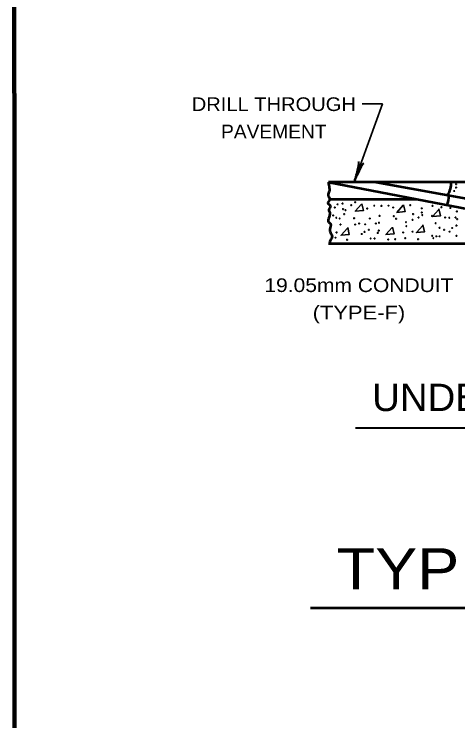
# Model space of a CAD drawing. Extents: x -90 to 623, y -379 to 75.
# Drawn here: x -42.6 to 22.4, y -132.1 to -28.7 of the extents above; entities that cross this region are included whole.
import ezdxf
from ezdxf.enums import TextEntityAlignment as Align

# ---------------------------------------------------------------- set-up
doc = ezdxf.new("R2010")
doc.units = 0
doc.header["$LTSCALE"] = 0.8
doc.layers.add('1', color=7, linetype='Continuous', lineweight=35)

msp = doc.modelspace()

# ---------------------------------------------------------------- linework, layer by layer
at = {"layer": '1', "lineweight": 53}
for p, q in [((33.4567, -53.3181), (3.4567, -53.3181)), ((3.4567, -53.3181), (31.9376, -58.7988)), ((10.4567, -53.3181), (32.4567, -57.3053)), ((3.4567, -55.8181), (16.448, -55.8181)), ((33.4567, -62.3181), (3.4567, -62.3181)), ((0.8544, -115.6087), (216.8702, -115.6087))]:
    msp.add_line(p, q, dxfattribs=at)
at = {"layer": '1', "lineweight": 40}
msp.add_line((7.4085, -89.2559), (100.8059, -89.2559), dxfattribs=at)
at = {"layer": '1', "lineweight": 158}
msp.add_lwpolyline([(617.1938, 69.4188), (-42.5562, 69.3355), (-42.4728, -368.9978)], dxfattribs=at)
at = {"layer": '1'}
for points in [[(7.2722, -53.1423), (11.3764, -41.866), (8.3764, -41.866)], [(8.3163, -56.5358), (7.3949, -57.5722), (8.5849, -57.4571), (8.3546, -56.459)], [(14.4199, -56.6893), (13.4986, -57.7258), (14.6886, -57.6107), (14.4582, -56.6126)], [(19.6023, -57.3035), (18.681, -58.34), (19.871, -58.2248), (19.6407, -57.2267)], [(6.2432, -60.0291), (5.3219, -61.0656), (6.5119, -60.9504), (6.2816, -59.9523)], [(12.8077, -59.9523), (11.8863, -60.9888), (13.0763, -60.8737), (12.846, -59.8756)], [(17.2607, -59.6452), (16.3393, -60.6817), (17.5293, -60.5665), (17.299, -59.5684)]]:
    msp.add_lwpolyline(points, dxfattribs=at)
for centre in [(22.1552, -53.5987), (21.8865, -54.5968), (22.1552, -54.0977), (4.8038, -56.5547), (5.5332, -56.4395), (6.8, -56.6698), (7.3758, -56.2475), (10.1782, -56.7466), (11.2147, -56.785), (12.2512, -56.7466), (15.4373, -56.6698), (18.7003, -56.785), (4.3816, -57.0153), (5.61, -57.2457), (5.7636, -57.975), (5.9555, -57.3992), (9.1417, -57.1688), (12.9422, -57.0153), (15.8596, -57.975), (17.1264, -57.1305), (17.1264, -57.7447), (20.0055, -56.9769), (21.3107, -57.0921), (22.2704, -57.5911), (4.1513, -58.1669), (4.6119, -58.5124), (5.1109, -58.6276), (7.2223, -58.5892), (9.5256, -58.6276), (10.9459, -58.2437), (13.0189, -58.2821), (13.3644, -58.666), (15.7828, -58.8196), (16.6657, -58.4741), (17.2032, -58.1286), (18.6236, -58.2437), (20.543, -58.4741), (21.1572, -58.5124), (22.0785, -58.4741), (22.3088, -58.7044), (5.2261, -59.5105), (7.3758, -59.5105), (7.9517, -59.357), (8.8346, -59.4722), (10.4085, -59.357), (10.8692, -59.2418), (14.8232, -59.165), (14.8615, -59.7408), (19.161, -59.3186), (19.7368, -59.9712), (21.5794, -60.0096), (22.1937, -59.6641), (4.6503, -60.6622), (8.3356, -60.8925), (8.7578, -60.5854), (9.372, -60.2782), (10.6772, -60.7389), (10.8308, -60.3934), (14.4008, -60.6622), (15.7828, -60.547), (20.3894, -60.2782), (21.1956, -60.547), (4.4967, -61.4299), (6.1858, -61.737), (9.6407, -61.5451), (10.2166, -61.5451), (12.2127, -61.6987), (13.2492, -61.6602), (14.708, -61.5067), (16.589, -61.6602), (18.6619, -61.1612), (18.8155, -61.5067), (19.2762, -61.238), (19.7368, -61.238), (22.1937, -61.1612)]:
    msp.add_circle(centre, 0.0607, dxfattribs=at)
at = {"layer": '1', "lineweight": 53}
for centre, radius, start, end in [((17.7204, -53.3079), 3.7363, 329.7014, 359.8431), ((18.9283, -55.4966), 2.1707, 327.00343, 7.84739)]:
    msp.add_arc(centre, radius, start, end, dxfattribs=at)
at = {"layer": '1', "lineweight": 40}
for centre, major_axis, ratio, start_param, end_param in [((7.3857, -52.0224), (-0.464, -1.7314), 0.122415, 0.89635335, 3.14159265), ((7.8542, -52.1618), (0.7658, 1.5904), 0.07063, 6.28230741, 8.55970261)]:
    msp.add_ellipse(centre, major_axis=major_axis, ratio=ratio, start_param=start_param, end_param=end_param, dxfattribs=at)
at = {"layer": '1', "lineweight": 53}
msp.add_spline([(3.4567, -53.3181), (3.5184, -53.7342), (3.5952, -54.5019), (3.4416, -55.0393), (3.4416, -55.3464), (3.6719, -55.8071), (3.3648, -56.3445), (3.7487, -56.8052), (3.5184, -57.3426), (3.6719, -57.7264), (3.6719, -57.9567), (3.4416, -58.8781), (3.4416, -59.0317), (3.7487, -59.4155), (3.6719, -60.1833), (3.7487, -60.7207), (3.979, -61.1046), (3.8255, -61.7188), (3.6719, -62.1027), (3.6719, -62.333), (3.4567, -62.3181)], degree=3, dxfattribs=at)

# ---------------------------------------------------------------- texts
at = {"layer": '1'}
for s, width, p in [('DRILL THROUGH', 1.1, (-4.5373, -42.8948)), ('PAVEMENT', 1.05, (-4.5373, -46.8948)), ('19.05mm CONDUIT', 1.15, (7.9264, -69.3843)), ('(TYPE-F)', 1.2, (7.9264, -73.3843))]:
    msp.add_text(s, height=2, dxfattribs=dict(at, width=width)).set_placement(p, align=Align.CENTER)
for s, height, width, p in [('UNDERGROUND INSTALLATION', 4, 1.05, (9.8662, -86.7986)), ('TYPICAL SECTION IN GUTTER AND SIDEWALK', 6, 1.15, (4.6777, -112.8777))]:
    msp.add_text(s, height=height, dxfattribs=dict(at, width=width)).set_placement(p)

doc.saveas('drawing.dxf')
